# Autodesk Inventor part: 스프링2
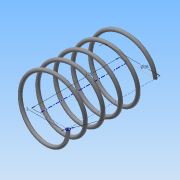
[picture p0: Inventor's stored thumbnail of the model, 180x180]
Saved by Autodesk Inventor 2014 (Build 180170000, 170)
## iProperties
Created: 2015-06
Part Number: 스프링2
Material: 강철, 연강
Document SubType Name: Modeling
Designer: MYHOME
Density: 7.86 g/cm^3
Appearance: 강철
Mass: 1.53479 g
Surface Area: 7.89194 cm^2
Volume: 0.195266 cm^3
Author: MYHOME
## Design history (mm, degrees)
sketch "스케치1"
  geometry: L1 (0, 0)-(8, 0); L2 (8, 0)-(8, 21.5); L3 (8, 21.5)-(0, 21.5); L4 (0, 21.5)-(0, 0); C1 r 0.5 at (8, 0)
  constraints: 8 end point, 2 parallel, 1 centre point, 1 coincident, 1 horizontal, 1 perpendicular
  dimensions: "d0" = 1 diameter of C1; "d1" = 16 diameter of L2 L4; "d2" = 21.5 distance of L3.end L1.start (derived)
feature "코일1" pitch "d3" = 10; turns "d5" = 5; dims "d4" = 21.5 (= d2), "d6" = 0, angle "d7" = 90 deg, angle "d8" = 90 deg, "d9" = 0, "d10" = 0
sketch "스케치2"
  geometry: L1 (-8.5, 0)-(-7.5, 0) reference; 1 further point
  constraints: 1 horizontal alignment
extrude "돌출1" cut sketch "스케치2" distance "d11" = 10; taper "d12" = 0 deg
node "작업 평면1"
sketch "스케치3"
  geometry: L1 (-7.5, 0)-(-8.5, 0) reference; 1 further point
  constraints: 1 horizontal alignment
extrude "돌출2" cut sketch "스케치3" distance "d14" = 10; taper "d15" = 0 deg
node "솔리드1"
node "절단 모서리 투영1"
node "절단 모서리 투영2"
other parameters: "d13" = 21.5 (= d2)
